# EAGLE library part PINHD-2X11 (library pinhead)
PIN HEADER
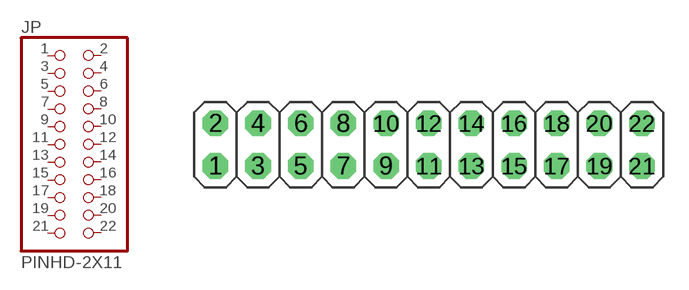
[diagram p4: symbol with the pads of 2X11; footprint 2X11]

Designator prefix JP

## PINHD-2X11  [2X11]
1  1  pas
2  2  pas
3  3  pas
4  4  pas
5  5  pas
6  6  pas
7  7  pas
8  8  pas
9  9  pas
10  10  pas
11  11  pas
12  12  pas
13  13  pas
14  14  pas
15  15  pas
16  16  pas
17  17  pas
18  18  pas
19  19  pas
20  20  pas
21  21  pas
22  22  pas

## Footprint 2X11 (pad centres in mm)
PIN HEADER
drill 1.016 octagon: 1 -12.7,-1.27; 2 -12.7,1.27; 3 -10.16,-1.27; 4 -10.16,1.27; 5 -7.62,-1.27; 6 -7.62,1.27; 7 -5.08,-1.27; 8 -5.08,1.27; 9 -2.54,-1.27; 10 -2.54,1.27; 11 0,-1.27; 12 0,1.27; 13 2.54,-1.27; 14 2.54,1.27; 15 5.08,-1.27; 16 5.08,1.27; 17 7.62,-1.27; 18 7.62,1.27; 19 10.16,-1.27; 20 10.16,1.27; 21 12.7,-1.27; 22 12.7,1.27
